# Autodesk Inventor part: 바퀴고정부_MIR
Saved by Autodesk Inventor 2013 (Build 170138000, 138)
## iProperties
Created: 2015-05
Part Number: 바퀴고정부_MIR
Material: 일반
Vendor: CBT Solutions
Document SubType Name: 모델링
Designer: Administrator
Company: 한국ATC센터
Author: KYOUNG IL JANG
Comments: 파생
d0: 1.000 ul
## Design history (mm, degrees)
derived "바퀴고정부.ipt" dims count "d0" = 1
feature "솔리드1::바퀴고정부.ipt" dims count "d0" = 1
tag "피쳐 태그1"
node "솔리드1"
